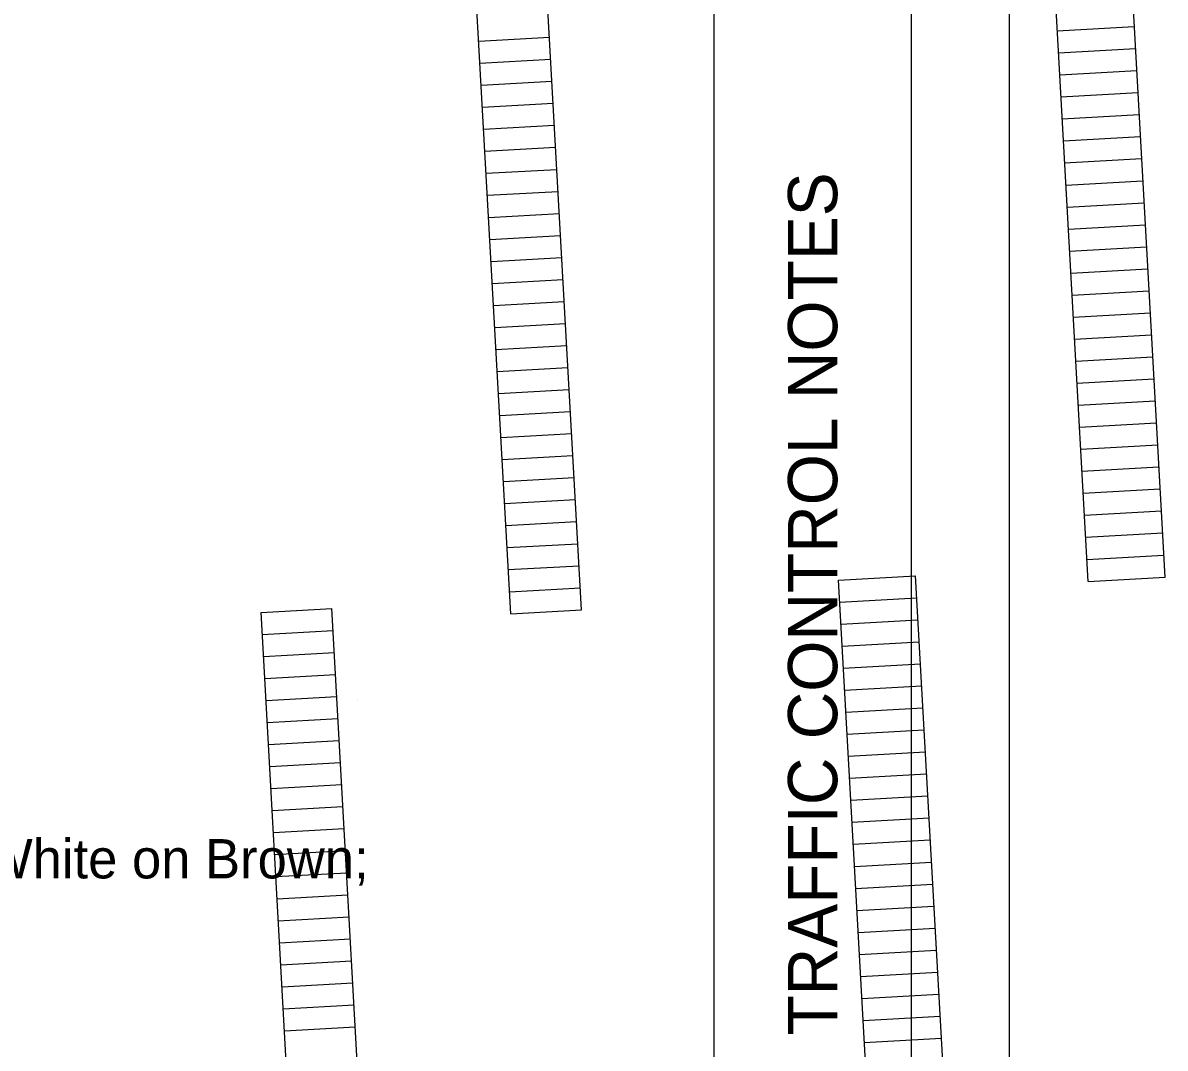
# Model space of a CAD drawing. Extents: x 1822205 to 1824724, y 710141 to 711863.
# Drawn here: x 1823790.9 to 1824080.9, y 710655 to 710915.3 of the extents above; entities that cross this region are included whole.
import ezdxf

# ---------------------------------------------------------------- set-up
doc = ezdxf.new("R2010")
doc.units = 0
for name, color, linetype in [('PM_P_Cells', 7, 'Continuous'), ('SC_Scratch1', 7, 'Continuous'), ('SH_Border', 7, 'Continuous'), ('SH_Cut_Line', 7, 'Continuous'), ('SH_Data', 7, 'Continuous')]:
    doc.layers.add(name, color=color, linetype=linetype)

msp = doc.modelspace()

# ---------------------------------------------------------------- linework, layer by layer
at = {"layer": 'SC_Scratch1'}
for p, q in [((1824080.9, 710774.61), (1824058.35, 711177.18)), ((1824061.33, 710773.51), (1824038.78, 711176.08)), ((1823932.73, 710766.31), (1823910.18, 711168.88)), ((1823914.76, 710765.3), (1823892.21, 711167.87)), ((1824053.5, 710913.29), (1824073.07, 710914.39)), ((1823906.61, 710910.67), (1823924.59, 710911.68)), ((1824053.81, 710907.7), (1824073.38, 710908.8)), ((1823906.93, 710905.08), (1823924.9, 710906.09)), ((1824054.12, 710902.11), (1824073.69, 710903.21)), ((1823907.24, 710899.49), (1823925.21, 710900.5)), ((1824054.44, 710896.52), (1824074.01, 710897.61)), ((1823907.55, 710893.9), (1823925.53, 710894.91)), ((1824054.75, 710890.93), (1824074.32, 710892.02)), ((1823907.87, 710888.31), (1823925.84, 710889.32)), ((1824055.06, 710885.34), (1824074.63, 710886.43)), ((1823908.18, 710882.72), (1823926.15, 710883.72)), ((1824055.38, 710879.74), (1824074.95, 710880.84)), ((1823908.49, 710877.13), (1823926.47, 710878.13)), ((1824055.69, 710874.15), (1824075.26, 710875.25)), ((1823908.81, 710871.53), (1823926.78, 710872.54)), ((1824056, 710868.56), (1824075.57, 710869.66)), ((1823909.12, 710865.94), (1823927.09, 710866.95)), ((1824056.32, 710862.97), (1824075.89, 710864.07)), ((1823909.43, 710860.35), (1823927.41, 710861.36)), ((1824056.63, 710857.38), (1824076.2, 710858.48)), ((1823909.75, 710854.76), (1823927.72, 710855.77)), ((1824056.94, 710851.79), (1824076.51, 710852.88)), ((1823910.06, 710849.17), (1823928.03, 710850.18)), ((1824057.26, 710846.2), (1824076.83, 710847.29)), ((1823910.37, 710843.58), (1823928.34, 710844.59)), ((1824057.57, 710840.61), (1824077.14, 710841.7)), ((1823910.69, 710837.99), (1823928.66, 710838.99)), ((1824057.88, 710835.01), (1824077.45, 710836.11)), ((1823911, 710832.4), (1823928.97, 710833.4)), ((1824058.2, 710829.42), (1824077.77, 710830.52)), ((1823911.31, 710826.81), (1823929.28, 710827.81)), ((1824058.51, 710823.83), (1824078.08, 710824.93)), ((1823911.63, 710821.21), (1823929.6, 710822.22)), ((1824058.82, 710818.24), (1824078.39, 710819.34)), ((1823911.94, 710815.62), (1823929.91, 710816.63)), ((1824059.14, 710812.65), (1824078.7, 710813.75)), ((1823912.25, 710810.03), (1823930.22, 710811.04)), ((1824059.45, 710807.06), (1824079.02, 710808.15)), ((1823912.57, 710804.44), (1823930.54, 710805.45)), ((1824059.76, 710801.47), (1824079.33, 710802.56)), ((1823912.88, 710798.85), (1823930.85, 710799.86)), ((1823913.19, 710793.26), (1823931.16, 710794.26)), ((1824060.08, 710795.88), (1824079.64, 710796.97)), ((1824060.39, 710790.28), (1824079.96, 710791.38)), ((1823913.5, 710787.67), (1823931.48, 710788.67)), ((1824060.7, 710784.69), (1824080.27, 710785.79)), ((1823913.82, 710782.08), (1823931.79, 710783.08)), ((1824061.01, 710779.1), (1824080.58, 710780.2)), ((1823914.13, 710776.48), (1823932.1, 710777.49)), ((1823997.93, 710773.83), (1824017.5, 710774.93)), ((1824040.05, 710372.36), (1824017.5, 710774.93)), ((1824061.33, 710773.51), (1824080.9, 710774.61)), ((1823914.44, 710770.89), (1823932.42, 710771.9)), ((1824020.48, 710371.27), (1823997.93, 710773.83)), ((1823998.24, 710768.24), (1824017.81, 710769.34)), ((1823851.36, 710765.62), (1823869.33, 710766.63)), ((1823873.91, 710363.06), (1823851.36, 710765.62)), ((1823891.88, 710364.06), (1823869.33, 710766.63)), ((1823914.76, 710765.3), (1823932.73, 710766.31)), ((1823998.56, 710762.65), (1824018.13, 710763.75)), ((1823851.67, 710760.03), (1823869.65, 710761.04)), ((1823998.87, 710757.06), (1824018.44, 710758.16)), ((1823851.99, 710754.44), (1823869.96, 710755.45)), ((1823999.18, 710751.47), (1824018.75, 710752.57)), ((1823852.3, 710748.85), (1823870.27, 710749.86)), ((1823999.5, 710745.88), (1824019.07, 710746.97)), ((1823852.61, 710743.26), (1823870.58, 710744.27)), ((1823875.92, 710743.5), (1823875.92, 710743.5)), ((1823999.81, 710740.29), (1824019.38, 710741.38)), ((1823852.93, 710737.67), (1823870.9, 710738.68)), ((1824000.12, 710734.7), (1824019.69, 710735.79)), ((1823853.24, 710732.08), (1823871.21, 710733.08)), ((1824000.44, 710729.1), (1824020.01, 710730.2)), ((1823853.55, 710726.49), (1823871.52, 710727.49)), ((1823853.87, 710720.89), (1823871.84, 710721.9)), ((1824000.75, 710723.51), (1824020.32, 710724.61)), ((1824001.06, 710717.92), (1824020.63, 710719.02)), ((1823854.18, 710715.3), (1823872.15, 710716.31)), ((1824001.38, 710712.33), (1824020.94, 710713.43)), ((1823854.49, 710709.71), (1823872.46, 710710.72)), ((1824001.69, 710706.74), (1824021.26, 710707.84)), ((1823854.8, 710704.12), (1823872.78, 710705.13)), ((1824002, 710701.15), (1824021.57, 710702.24)), ((1823855.12, 710698.53), (1823873.09, 710699.54)), ((1824002.31, 710695.56), (1824021.88, 710696.65)), ((1823855.43, 710692.94), (1823873.4, 710693.95)), ((1824002.63, 710689.97), (1824022.2, 710691.06)), ((1823855.74, 710687.35), (1823873.72, 710688.35)), ((1824002.94, 710684.37), (1824022.51, 710685.47)), ((1823856.06, 710681.76), (1823874.03, 710682.76)), ((1824003.25, 710678.78), (1824022.82, 710679.88)), ((1823856.37, 710676.16), (1823874.34, 710677.17)), ((1824003.57, 710673.19), (1824023.14, 710674.29)), ((1823856.68, 710670.57), (1823874.66, 710671.58)), ((1824003.88, 710667.6), (1824023.45, 710668.7)), ((1823857, 710664.98), (1823874.97, 710665.99)), ((1824004.19, 710662.01), (1824023.76, 710663.11)), ((1823857.31, 710659.39), (1823875.28, 710660.4)), ((1824004.51, 710656.42), (1824024.08, 710657.51))]:
    msp.add_line(p, q, dxfattribs=at)
at = {"layer": 'SH_Border'}
msp.add_line((1823966.39, 710166.46), (1823966.39, 711216.46), dxfattribs=at)
msp.add_lwpolyline([(1822441.39, 711216.46), (1824016.39, 711216.46), (1824016.39, 710166.46), (1822441.39, 710166.46)], close=True, dxfattribs=at)
at = {"layer": 'SH_Cut_Line'}
msp.add_lwpolyline([(1822341.39, 710141.46), (1824041.39, 710141.46), (1824041.39, 711241.46), (1822341.39, 711241.46)], close=True, dxfattribs=at)

# ---------------------------------------------------------------- texts
at = {"layer": 'PM_P_Cells'}
msp.add_text('1.50" Radius, 0.63" Border, 0.38" Indent, White on Brown; ', height=9.9781, dxfattribs=at).set_placement((1823536.61, 710698.08))
at = {"layer": 'SH_Data'}
msp.add_text('TRAFFIC CONTROL NOTES', height=12.5, rotation=90, dxfattribs=at).set_placement((1823997.64, 710658.19))

doc.saveas('drawing.dxf')
